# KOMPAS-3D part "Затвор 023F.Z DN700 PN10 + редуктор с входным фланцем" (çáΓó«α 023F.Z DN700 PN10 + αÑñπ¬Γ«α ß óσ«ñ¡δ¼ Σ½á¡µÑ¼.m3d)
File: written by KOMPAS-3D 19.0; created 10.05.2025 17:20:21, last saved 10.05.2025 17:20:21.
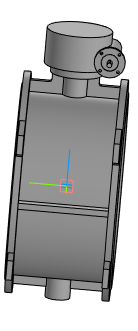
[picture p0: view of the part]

Document properties: Полное имя файла: Затвор 023F.Z DN700 PN10 + редуктор с входным фланцем.a3d

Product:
- Part/product: Затвор 023F.Z DN700 PN10 + редуктор с входным фланцем
    Масса: 559.761

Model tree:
1. Операция без истории:1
